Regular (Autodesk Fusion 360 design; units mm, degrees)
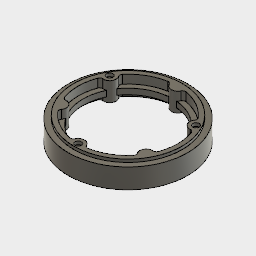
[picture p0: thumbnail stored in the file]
parameter "height" = 23 comment "height of the component"
parameter "rail_height" = 3
parameter "exrtusion_delta_for_magnets" = 0.8
parameter "diameter" = 120
parameter "inner_diameter" = 100
parameter "diameter_offet" = 10
parameter "pressfit_offset" = 1
parameter "magnet_diameter" = 6.4
parameter "magnet_height" = 3.2
parameter "holes_position_from_diameter" = 20
parameter "plateform_height" = 5.75 (= "height / 4")
parameter "plateform_inner_diameter" = 90
sketch "base" plane through (0, 0, 0) normal (0, 1, 0) x axis (1, 0, 0)
  circle C1 centre (0, 0) radius 60
  circle C2 centre (0, 0) radius 50
  dimension "d1" diameter C1 = 120 (= "diameter")
  dimension "d63" diameter C2 = 100 (= "inner_diameter")
sketch "arround magnets" plane through (0, 0, 0) normal (0, 1, 0) x axis (1, 0, 0)
  circle C1 centre (0, 50) radius 6.4
  point P1 (0, 0)
  point P2 (0, 50)
  dimension "d124" diameter C1 = 12.8 (= "magnet_diameter * 2")
  dimension "d130" distance P1 P2 = 50 (= "diameter / 2 - holes_position_from_diameter / 2")
extrude "Extrude18" new body sketch "arround magnets" along normal blind 23 (= "height")
circular_pattern "C-Pattern6" TotalAngle 360
extrude "Extrude17" new body sketch "base" profile of C2 along normal blind 23 (= "height")
extrude "Extrude8" new body sketch "base" along normal blind 23 (= "height") bodies "Part A Top"
combine "Combine2"
sketch "top_holes" plane through (0, 23, 0) normal (0, 1, 0) x axis (-1, 0, 0)
  circle C1 centre (0, 50) radius 3.2
  circle C2 centre (-43.3013, -25) radius 3.2
  circle C3 centre (43.3013, -25) radius 3.2
  point P1 (0, 0)
  point P4 (43.3013, -25)
  dimension "d5" diameter C1 = 6.4 (= "magnet_diameter")
  dimension "d94" distance P1 P4 = 50 (= "diameter / 2 - holes_position_from_diameter / 2")
  dimension "d7" C-Pattern1-Angle = 360
extrude "Extrude13" cut sketch "top_holes" no distance stored
sketch "top_rail_out" plane through (0, 23, 0) normal (0, 1, 0) x axis (-1, 0, 0)
  circle C1 centre (0, 0) radius 60
  circle C2 centre (0, 0) radius 54.5
  circle C3 centre (-43.3013, -25) radius 3.2
  circle C4 centre (0, 50) radius 3.2
  circle C5 centre (43.3013, -25) radius 3.2
  arc A1 centre (-43.3013, 25) radius 6.4 clockwise from (-39.7531, 30.3264) to (-46.14, 19.264)
  arc A2 centre (0, 50) radius 6.4 clockwise from (6.3869, 49.5904) to (-6.3869, 49.5904)
  arc A3 centre (43.3013, 25) radius 6.4 clockwise from (46.14, 19.264) to (39.7531, 30.3264)
  arc A4 centre (43.3013, -25) radius 6.4 clockwise from (39.7531, -30.3264) to (46.14, -19.264)
  arc A5 centre (0, -50) radius 6.4 clockwise from (-6.3869, -49.5904) to (6.3869, -49.5904)
  arc A6 centre (-43.3013, -25) radius 6.4 clockwise from (-46.14, -19.264) to (-39.7531, -30.3264)
  arc A7 centre (0, 0) radius 50 clockwise from (-46.14, -19.264) to (-46.14, 19.264)
  arc A8 centre (0, 0) radius 50 clockwise from (-39.7531, 30.3264) to (-6.3869, 49.5904)
  arc A9 centre (0, 0) radius 50 clockwise from (6.3869, 49.5904) to (39.7531, 30.3264)
  arc A10 centre (0, 0) radius 50 clockwise from (46.14, 19.264) to (46.14, -19.264)
  arc A11 centre (0, 0) radius 50 clockwise from (39.7531, -30.3264) to (6.3869, -49.5904)
  arc A12 centre (0, 0) radius 50 clockwise from (-6.3869, -49.5904) to (-39.7531, -30.3264)
  circle C6 centre (0, 0) radius 60
  dimension "d65" diameter C2 = 109 (= "diameter - diameter_offet - pressfit_offset")
  dimension "d96" diameter C1 = 120 (= "diameter")
extrude "Extrude10" cut sketch "top_rail_out" profile of C1 C2 against normal blind 3 (magnitude of "-1 * rail_height")
sketch "bottom_holes" plane through (0, 0, 0) normal (0, -1, 0) x axis (1, 0, 0)
  circle C1 centre (-43.3013, 25) radius 3.2
  point P1 (0, 0)
  point P2 (-43.3013, 25)
  dimension "d57" diameter C1 = 6.4 (= "magnet_diameter")
  dimension "d95" distance P1 P2 = 50 (= "diameter / 2 - holes_position_from_diameter / 2")
extrude "Extrude14" cut sketch "bottom_holes" no distance stored
sketch "top_rail_in" plane through (0, 23, 0) normal (0, 1, 0) x axis (-1, 0, 0)
  circle C1 centre (56.2917, -32.5) radius 3.175
  circle C2 centre (0, 65) radius 3.175
  circle C3 centre (-56.2917, -32.5) radius 3.175
  circle C4 centre (0, 0) radius 75
  circle C5 centre (0, 0) radius 70
  circle C6 centre (0, 0) radius 60
  circle C7 centre (0, 0) radius 50
  circle C8 centre (0, 0) radius 60
  arc A1 centre (-43.3013, 25) radius 6.4 clockwise from (-39.7531, 30.3264) to (-46.14, 19.264)
  arc A2 centre (0, 50) radius 6.4 clockwise from (6.3869, 49.5904) to (-6.3869, 49.5904)
  arc A3 centre (43.3013, 25) radius 6.4 clockwise from (46.14, 19.264) to (39.7531, 30.3264)
  arc A4 centre (43.3013, -25) radius 6.4 clockwise from (39.7531, -30.3264) to (46.14, -19.264)
  arc A5 centre (0, -50) radius 6.4 clockwise from (-6.3869, -49.5904) to (6.3869, -49.5904)
  arc A6 centre (-43.3013, -25) radius 6.4 clockwise from (-46.14, -19.264) to (-39.7531, -30.3264)
  circle C9 centre (-43.3013, -25) radius 3.2
  circle C10 centre (0, 50) radius 3.2
  circle C11 centre (43.3013, -25) radius 3.2
  circle C12 centre (0, 0) radius 54.5
  arc A7 centre (0, 0) radius 50 clockwise from (-46.14, -19.264) to (-46.14, 19.264)
  arc A8 centre (0, 0) radius 50 clockwise from (-39.7531, 30.3264) to (-6.3869, 49.5904)
  arc A9 centre (0, 0) radius 50 clockwise from (6.3869, 49.5904) to (39.7531, 30.3264)
  arc A10 centre (0, 0) radius 50 clockwise from (46.14, 19.264) to (46.14, -19.264)
  arc A11 centre (0, 0) radius 50 clockwise from (39.7531, -30.3264) to (6.3869, -49.5904)
  arc A12 centre (0, 0) radius 50 clockwise from (-6.3869, -49.5904) to (-39.7531, -30.3264)
  dimension "d35" diameter C6 = 120 (= "diameter")
  dimension "d64" diameter C7 = 100 (= "inner_diameter")
  dimension "d66" diameter C8 = 120 (= "diameter")
work_plane "WorkPlane1" AlongDistance -11.5 (= "-1 * height / 2")
work_point "WorkPoint1"
work_axis "WorkAxis1"
circular_pattern "C-Pattern1" TotalAngle 360
sketch "bottom_rail_out" plane through (0, 0, 0) normal (0, -1, 0) x axis (1, 0, 0)
  circle C1 centre (0, 0) radius 55
  circle C2 centre (0, -50) radius 3.2
  circle C3 centre (43.3013, 25) radius 3.2
  circle C4 centre (-43.3013, 25) radius 3.2
  arc A1 centre (0, -50) radius 6.4 clockwise from (-6.3869, -49.5904) to (6.3869, -49.5904)
  arc A2 centre (-43.3013, 25) radius 55.4401 clockwise from (-46.14, -19.264) to (-39.7531, -30.3264)
  arc A3 centre (-43.3013, 25) radius 6.4 clockwise from (-39.7531, 30.3264) to (-46.14, 19.264)
  arc A4 centre (43.3013, 25) radius 55.4401 clockwise from (6.3869, 49.5904) to (-6.3869, 49.5904)
  arc A5 centre (43.3013, 25) radius 6.4 clockwise from (46.14, 19.264) to (39.7531, 30.3264)
  arc A6 centre (0, -50) radius 55.4401 clockwise from (39.7531, -30.3264) to (46.14, -19.264)
  arc A7 centre (0, 0) radius 50 clockwise from (39.7531, -30.3264) to (6.3869, -49.5904)
  arc A8 centre (0, 0) radius 50 clockwise from (-6.3869, -49.5904) to (-39.7531, -30.3264)
  arc A9 centre (0, 0) radius 50 clockwise from (-46.14, -19.264) to (-46.14, 19.264)
  arc A10 centre (0, 0) radius 50 clockwise from (-39.7531, 30.3264) to (-6.3869, 49.5904)
  arc A11 centre (0, 0) radius 50 clockwise from (6.3869, 49.5904) to (39.7531, 30.3264)
  arc A12 centre (0, 0) radius 50 clockwise from (46.14, 19.264) to (46.14, -19.264)
  circle C5 centre (0, 0) radius 60
  dimension "d67" diameter C1 = 110 (= "diameter - diameter_offet")
extrude "Extrude15" cut sketch "bottom_rail_out" profile of C1 against normal blind 3.8 (magnitude of "-1 * rail_height - exrtusion_delta_for_magnets")
fillet "Fillet3" radius 3
sketch "Sketch19" plane through (0, 0, 0) normal (0, 1, 0) x axis (1, 0, 0)
  circle C1 centre (0, 0) radius 45
  circle C2 centre (0, 0) radius 50
  dimension "d132" diameter C1 = 90 (= "plateform_inner_diameter")
  dimension "d134" diameter C2 = 100 (= "inner_diameter")
extrude "Extrude19" add sketch "Sketch19" distance 5.75 (= "plateform_height") from offset 11.5 (= "height / 2")
named bodies: "Part A Top"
